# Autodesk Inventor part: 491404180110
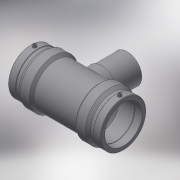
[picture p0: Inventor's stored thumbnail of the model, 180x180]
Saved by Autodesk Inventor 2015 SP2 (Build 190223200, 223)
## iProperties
Created: 2017-06
Part Number: 491404180110
Material: Generic
Description: PLASSON REDUCING TEE 180x110x180
Document SubType Name: Modeling
Designer: KIM
Mass: 7728.34 g
Surface Area: 6460.51 cm^2
Volume: 7728.34 cm^3
Density: 1 g/cm^3
Appearance: Default
Author: KIM
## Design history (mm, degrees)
derived "491404.ipt"
feature "Solid1::491404.ipt"
tag "TaggingFeature1"
body "Solid1"
other parameters: "d0" = 422, "d2" = 245, "d3" = 106, "d4" = 84.4, "d5" = 220.5, "d6" = 171, "d8" = 168 deg, "d10" = 42.4, "d11" = 14.13333, "d13" = 422, "d14" = 17.6296, "d17" = 162, "d19" = 3.52592, "d20" = 168 deg, "d22" = 227.85, "d23" = 245, "d25" = 135 deg, "d26" = 295.4, "d29" = 116, "d30" = 15, "d31" = 168.8, "d34" = 5 deg, "d35" = 15, "d39" = 5 deg, "d41" = 4, "d42" = 14, "d43" = 0, "d45" = 4, "d46" = 6, "d47" = 0, "d48" = -219, "d51" = 0, "d52" = 88, "d54" = 0, "d55" = 220.5, "d56" = 245, "d57" = 147.7, "d58" = 135 deg, "d59" = 106, "d60" = 106, "d61" = 135 deg, "d62" = 219, "d72" = 192.01, "d73" = 96.005, "d74" = -219, "d75" = 115.5, "d77" = 0, "d78" = 88, "d80" = 0, "d82" = 96.5, "d83" = 0, "d84" = 3, "d85" = 0, "d86" = 35.33333, "d87" = 223.293, "d88" = 14.13333, "d89" = 3, "d90" = 0, "L_" = 422, "L_1" = 106, "D_" = 245, "A_" = 116, "d_2" = 12, "H_" = 219
